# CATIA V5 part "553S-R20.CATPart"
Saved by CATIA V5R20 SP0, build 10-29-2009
Part number: 553S-R20
Definition: NONE
Nomenclature: 553S-R20
Source: Unknown
Description: 553S-R20
Bounding box of the stored display mesh (mm): x -11.25 to 11.25, y -12.329 to 12.49, z -0.6 to 0.6
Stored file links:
  C:\Users\Utente\Desktop\IO LAVORO\3D X SITO CF\X SITO\PLASTICA\553S\553S-R20.CATPart
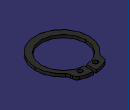
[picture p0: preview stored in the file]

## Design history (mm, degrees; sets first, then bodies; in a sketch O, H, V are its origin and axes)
Body1 "553S-R20" (main body)
  Solid1: solid without history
